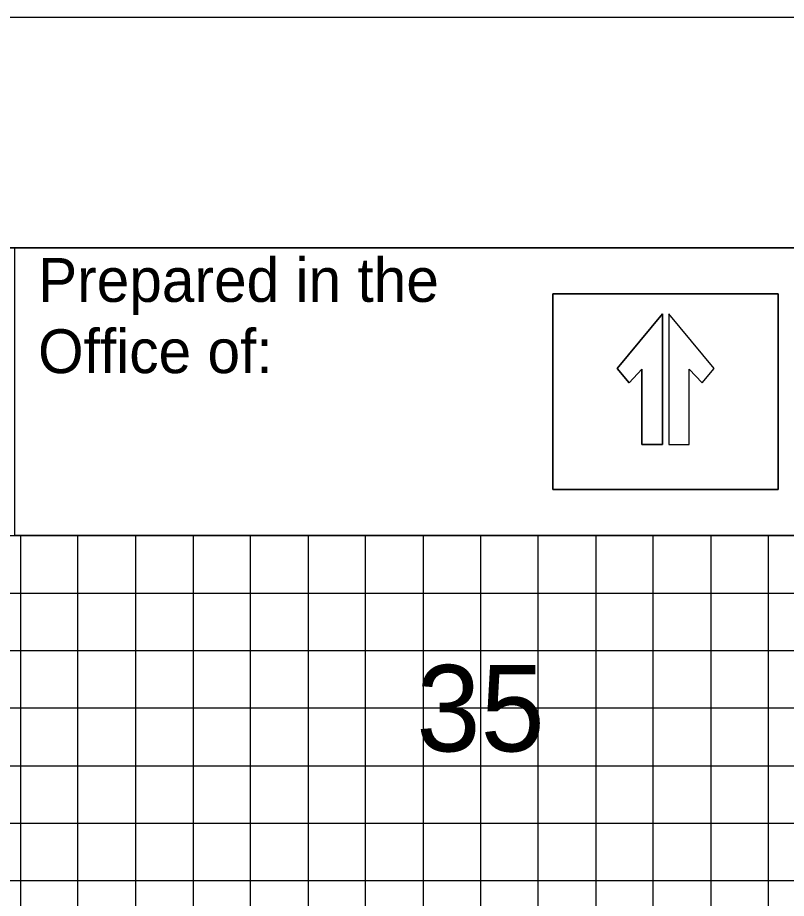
# Model space of a CAD drawing. Extents: x -7 to 162, y -2 to 107.
# Drawn here: x 110.98 to 117.66, y 99.35 to 107 of the extents above; entities that cross this region are included whole.
import ezdxf

# ---------------------------------------------------------------- set-up
doc = ezdxf.new("R2010")
doc.units = 0
for name, color, linetype in [('Prop DSN Text', 7, 'Continuous'), ('Prop North Arrow for Plan Sheets CELL', 7, 'Continuous'), ('Prop XS Offset Labels', 7, 'Continuous'), ('Sheet Block Title CELL', 7, 'Continuous'), ('Sheet Cross Section CELL', 7, 'Continuous'), ('Sheet Cross Section Grid Major CELL', 7, 'Continuous'), ('Sheet Cross Section Grid Middle CELL', 7, 'Continuous'), ('Sheet Cross Section Grid Minor 1 CELL', 7, 'Continuous'), ('Sheet Cross Section Grid Minor 2 CELL', 7, 'Continuous'), ('Sheet Plot Border Inside CELL', 7, 'Continuous'), ('Sheet Plot Border Outside CELL', 7, 'Continuous')]:
    doc.layers.add(name, color=color, linetype=linetype)

msp = doc.modelspace()

# ---------------------------------------------------------------- linework, layer by layer
at = {"layer": 'Prop North Arrow for Plan Sheets CELL'}
for points in [[(117.584, 104.5995), (115.6266, 104.5995), (115.6266, 102.9005), (117.584, 102.9005), (117.584, 104.5995)], [(116.5788, 104.4257), (116.5788, 103.2897), (116.3999, 103.2897), (116.3999, 103.945), (116.2891, 103.8276), (116.1849, 103.9521), (116.5788, 104.4257)], [(116.1849, 103.9521), (116.2891, 103.8276), (116.3999, 103.945), (116.3999, 103.2897), (116.5788, 103.2897), (116.5788, 104.4257), (116.1849, 103.9521)], [(116.6339, 104.4257), (116.6339, 103.2897), (116.8129, 103.2897), (116.8129, 103.945), (116.9237, 103.8276), (117.0279, 103.9521), (116.6339, 104.4257)]]:
    msp.add_lwpolyline(points, dxfattribs=at)
for points in [[(115.6266, 104.5995), (117.584, 104.5995), (117.584, 102.9005), (115.6266, 102.9005)], [(116.6339, 104.4257), (116.6339, 103.2897), (116.8129, 103.2897), (116.8129, 103.945), (116.9237, 103.8276), (117.0279, 103.9521)]]:
    msp.add_lwpolyline(points, close=True, dxfattribs=at)
at = {"layer": 'Sheet Block Title CELL'}
msp.add_lwpolyline([(110.9512, 105), (130, 105), (130, 102.5), (110.9512, 102.5)], close=True, dxfattribs=at)
at = {"layer": 'Sheet Cross Section CELL'}
msp.add_lwpolyline([(160, 105), (0, 105), (0, 0), (160, 0)], close=True, dxfattribs=at)
at = {"layer": 'Sheet Cross Section Grid Major CELL'}
for p, q in [((115, 105), (110, 105)), ((115, 0), (115, 102.5))]:
    msp.add_line(p, q, dxfattribs=at)
msp.add_lwpolyline([(0, 100), (160, 100)], dxfattribs=at)
at = {"layer": 'Sheet Cross Section Grid Middle CELL'}
for points in [[(72.5, 0), (77.5, 0), (77.5, 105), (82.5, 105), (82.5, 0), (87.5, 0), (87.5, 105), (92.5, 105), (92.5, 0), (97.5, 0), (97.5, 105), (102.5, 105), (102.5, 0), (107.5, 0), (107.5, 105), (112.5, 105)], [(117.5, 105), (122.5, 105)], [(0, 102.5), (137.5, 102.5)], [(112.5, 102.5), (112.5, 0), (117.5, 0), (117.5, 102.5)]]:
    msp.add_lwpolyline(points, dxfattribs=at)
at = {"layer": 'Sheet Cross Section Grid Minor 1 CELL'}
msp.add_line((0, 102), (160, 102), dxfattribs=at)
for points in [[(0, 101.5), (135, 101.5), (160, 101.5)], [(160, 101), (0, 101)], [(0, 100.5), (160, 100.5)], [(160, 99.5), (0, 99.5)]]:
    msp.add_lwpolyline(points, dxfattribs=at)
at = {"layer": 'Sheet Cross Section Grid Minor 2 CELL'}
for points in [[(110, 0), (110.5, 0), (110.5, 105), (111, 105)], [(111.5, 105), (112, 105)], [(113, 105), (113.5, 105)], [(114, 105), (114.5, 105)], [(115.5, 105), (116, 105)], [(116.5, 105), (117, 105)], [(111, 102.5), (111, 0)], [(111, 0), (111.5, 0), (111.5, 102.5)], [(112, 102.5), (112, 0)], [(112.5, 0), (113, 0), (113, 102.5)], [(113.5, 102.5), (113.5, 0)], [(113.5, 0), (114, 0), (114, 102.5)], [(114.5, 102.5), (114.5, 0)], [(115, 0), (115.5, 0), (115.5, 102.5)], [(116, 102.5), (116, 0)], [(116, 0), (116.5, 0), (116.5, 102.5)], [(117, 102.5), (117, 0)]]:
    msp.add_lwpolyline(points, dxfattribs=at)
at = {"layer": 'Sheet Plot Border Inside CELL'}
msp.add_lwpolyline([(-5.4, -0.5), (161.2, -0.5), (161.2, 105), (-5.4, 105)], close=True, dxfattribs=at)
at = {"layer": 'Sheet Plot Border Outside CELL'}
msp.add_lwpolyline([(-6.7, -2.5), (161.65, -2.5), (161.65, 107), (-6.7, 107)], close=True, dxfattribs=at)

# ---------------------------------------------------------------- texts
at = {"layer": 'Prop DSN Text'}
for s, height, p in [('Prepared in the ', 0.380976, (111.1533, 104.5302)), ('Office of:', 0.38098, (111.1533, 103.9112))]:
    msp.add_text(s, height=height, rotation=360, dxfattribs=at).set_placement(p)
at = {"layer": 'Prop XS Offset Labels'}
msp.add_text('35', height=0.75, dxfattribs=at).set_placement((114.4408, 100.625))

doc.saveas('drawing.dxf')
